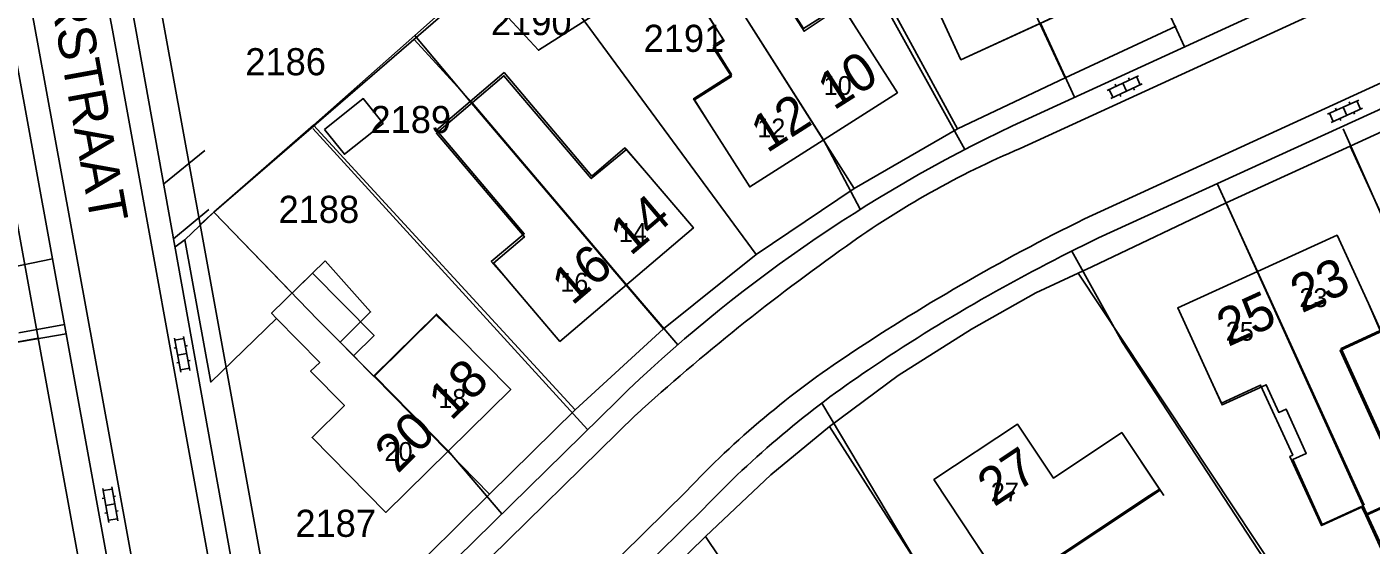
# Model space of a CAD drawing. Extents: x 148816 to 151297, y 399515 to 402500.
# Drawn here: x 149244.9 to 149334.2, y 399907.3 to 399941.7 of the extents above; entities that cross this region are included whole.
import ezdxf

# ---------------------------------------------------------------- set-up
doc = ezdxf.new("R2010")
doc.units = 0
for name, color, linetype in [('B01 Hoofdgebouw  [D] Norm', 7, 'Continuous'), ('B01 Hoofdgebouw  [T] Norm', 7, 'Continuous'), ('B01 hoofgebouw', 7, 'Continuous'), ('B02 Bijgebouw  [D] Norm', 7, 'Continuous'), ('B07 Tussenmuur  [T] Norm', 7, 'Continuous'), ('G01 perceelsgrens', 7, 'Continuous'), ('S02 Open verharding  Norm', 7, 'Continuous'), ('T04 Haag heg  [D] Gem', 7, 'Continuous'), ('V00 Kant verharding algemeen  [T] Norm', 7, 'Continuous'), ('Z01 perceelnummer', 7, 'Continuous'), ('Z02 huisnummer', 7, 'Continuous'), ('Z02 Huisnummer  [Tekst] Norm', 7, 'Continuous'), ('Z06 straatnaam', 7, 'Continuous')]:
    doc.layers.add(name, color=color, linetype=linetype)

msp = doc.modelspace()

# ---------------------------------------------------------------- linework, layer by layer
at = {"layer": 'B01 Hoofdgebouw  [D] Norm'}
for points in [[(149290.26, 399935.28), (149289.272, 399936.83), (149291.725, 399938.394), (149290.517, 399940.289), (149291.238, 399940.749), (149289.636, 399943.26), (149291.201, 399944.259), (149289.588, 399946.785), (149292.089, 399948.382), (149296.556, 399941.387), (149299.081, 399943.065), (149300.06, 399941.53)], [(149277.1, 399924.61), (149275.923, 399925.995), (149277.978, 399927.742), (149272.13, 399934.622), (149276.615, 399938.434), (149282.421, 399931.603), (149284.77, 399933.539), (149285.96, 399932.14)], [(149261.514, 399922.329), (149257.143, 399918.099), (149255.424, 399927.554), (149257.34, 399929.39), (149262.549, 399924.008)], [(149263.909, 399925.338), (149267.998, 399921.189), (149266.63, 399919.841), (149267.956, 399918.495), (149272.136, 399922.615), (149273.56, 399921.17)], [(149323.46, 399918.47), (149324.319, 399916.59), (149327.248, 399917.928), (149328.087, 399916.092), (149328.569, 399916.312), (149329.91, 399913.373), (149329.013, 399912.964), (149330.976, 399908.658), (149333.59, 399909.85), (149333.869, 399909.239), (149336.589, 399910.481), (149332.155, 399920.191), (149334.763, 399921.382), (149334.888, 399921.458), (149334.04, 399923.31)], [(149307.94, 399907.46), (149310.085, 399904.22), (149320.211, 399910.923)]]:
    msp.add_lwpolyline(points, dxfattribs=at)
at = {"layer": 'B01 Hoofdgebouw  [T] Norm'}
for p, q in [((149304.88, 399944.03), (149306.97, 399939.49)), ((149306.97, 399939.49), (149317.54, 399944.36)), ((149302.75, 399937.31), (149300.06, 399941.53)), ((149292.95, 399931.06), (149302.75, 399937.31)), ((149290.26, 399935.28), (149292.95, 399931.06)), ((149289.2, 399928.33), (149285.96, 399932.14)), ((149280.34, 399920.8), (149289.2, 399928.33)), ((149331.96, 399927.85), (149321.38, 399923.02)), ((149334.04, 399923.31), (149331.96, 399927.85)), ((149262.549, 399924.008), (149263.909, 399925.338)), ((149277.1, 399924.61), (149280.34, 399920.8)), ((149264.38, 399919.4), (149261.514, 399922.329)), ((149321.38, 399923.02), (149323.46, 399918.47)), ((149273.56, 399921.17), (149277.07, 399917.61)), ((149263.78, 399918.82), (149264.38, 399919.4)), ((149266.02, 399916.54), (149263.78, 399918.82)), ((149277.07, 399917.61), (149268.77, 399909.45)), ((149263.87, 399914.43), (149266.02, 399916.54)), ((149310.73, 399915.32), (149305.18, 399911.63)), ((149313.12, 399911.73), (149310.73, 399915.32)), ((149268.77, 399909.45), (149263.87, 399914.43)), ((149317.66, 399914.75), (149313.12, 399911.73)), ((149320.211, 399910.923), (149317.66, 399914.75)), ((149305.18, 399911.63), (149307.94, 399907.46))]:
    msp.add_line(p, q, dxfattribs=at)
at = {"layer": 'B01 hoofgebouw'}
for points in [[(149290.26, 399935.281), (149289.21, 399936.91), (149291.74, 399938.52), (149290.53, 399940.43), (149291.19, 399940.85), (149289.58, 399943.39), (149291.23, 399944.43), (149289.61, 399946.98), (149289.68, 399947.03), (149292.07, 399948.55), (149296.51, 399941.56), (149299.02, 399943.15), (149300.06, 399941.531)], [(149304.88, 399944.031), (149306.97, 399939.49), (149317.54, 399944.36), (149315.45, 399948.9)], [(149290.26, 399935.281), (149292.95, 399931.06), (149302.75, 399937.31), (149300.06, 399941.531)], [(149277.1, 399924.61), (149275.78, 399926.1), (149277.97, 399927.95), (149272.14, 399934.83), (149274.38, 399936.73), (149276.63, 399938.64), (149282.45, 399931.77), (149284.65, 399933.64), (149285.96, 399932.14)], [(149277.1, 399924.61), (149280.34, 399920.8), (149289.2, 399928.33), (149285.96, 399932.14)], [(149261.514, 399922.329), (149257.143, 399918.099), (149255.424, 399927.554), (149257.34, 399929.39)], [(149334.04, 399923.31), (149331.96, 399927.85), (149321.38, 399923.02), (149323.46, 399918.47)], [(149261.514, 399922.329), (149261.18, 399922.67), (149264.75, 399926.16)], [(149273.56, 399921.17), (149272.12, 399922.55), (149267.99, 399918.47), (149265.733, 399920.743), (149267.76, 399922.756), (149264.75, 399926.16)], [(149333.64, 399909.98), (149333.93, 399909.35), (149336.66, 399910.6), (149332.22, 399920.33), (149334.83, 399921.52), (149334.04, 399923.31)], [(149273.56, 399921.17), (149277.07, 399917.61), (149268.77, 399909.45), (149263.87, 399914.43), (149266.02, 399916.54), (149263.78, 399918.82), (149264.38, 399919.4), (149261.514, 399922.329)], [(149323.46, 399918.47), (149324.28, 399916.71), (149326.88, 399917.9), (149329.01, 399913.26), (149328.83, 399913.17), (149330.93, 399908.58), (149333.7, 399909.85)], [(149320.44, 399910.58), (149317.66, 399914.75), (149313.12, 399911.73), (149310.73, 399915.32), (149305.18, 399911.63), (149307.94, 399907.46)], [(149319.495, 399910.568), (149320.155, 399911.006)], [(149307.94, 399907.46), (149310.03, 399904.28), (149319.495, 399910.568)]]:
    msp.add_lwpolyline(points, dxfattribs=at)
at = {"layer": 'B02 Bijgebouw  [D] Norm'}
msp.add_lwpolyline([(149268.691, 399958.487), (149269.277, 399955.441), (149274.31, 399956.364), (149275.058, 399951.314), (149272.262, 399950.778), (149272.971, 399947.123), (149271.361, 399945.69), (149273.526, 399943.341), (149274.88, 399944.497), (149278.908, 399940.131), (149282.478, 399942.384)], dxfattribs=at)
msp.add_lwpolyline([(149264.705, 399934.868), (149267.278, 399936.917), (149268.591, 399935.269), (149266.018, 399933.22)], close=True, dxfattribs=at)
at = {"layer": 'B07 Tussenmuur  [T] Norm'}
for p, q in [((149297.85, 399934.185), (149291.36, 399944.361)), ((149284.77, 399924.565), (149274.506, 399936.642)), ((149326.67, 399925.435), (149333.751, 399909.924)), ((149272.92, 399913.53), (149267.998, 399918.536))]:
    msp.add_line(p, q, dxfattribs=at)
at = {"layer": 'G01 perceelsgrens'}
for points in [[(149300.56, 399967.54), (149307.02, 399953.24), (149308.46, 399950.09), (149309.3, 399948.28), (149312.22, 399941.91), (149313.9, 399938.29)], [(149290.46, 399964.82), (149293.95, 399958.5), (149294.23, 399958.63), (149297.78, 399951.64), (149297.67, 399951.58), (149306.74, 399934.91)], [(149280.18, 399962.03), (149289.68, 399947.03), (149299.88, 399930.96)], [(149252.94, 399947.74), (149256.45, 399928.57)], [(149270.69, 399941.11), (149277.94, 399947.54)], [(149277.94, 399947.54), (149293.37, 399926.57)], [(149263.98, 399935.16), (149270.69, 399941.11)], [(149270.69, 399941.11), (149274.38, 399936.73), (149284.74, 399924.53), (149287.21, 399921.63)], [(149313.9, 399938.29), (149321.28, 399941.73)], [(149306.74, 399934.91), (149313.9, 399938.29)], [(149332.82, 399933.76), (149341.05, 399937.51)], [(149242.794, 399936.73), (149245.678, 399921.012)], [(149257.34, 399929.39), (149263.98, 399935.16)], [(149263.98, 399935.16), (149281.35, 399916.26)], [(149299.88, 399930.96), (149306.74, 399934.91)], [(149324.6, 399930), (149332.82, 399933.76)], [(149332.82, 399933.76), (149342.22, 399913.25), (149344.91, 399907.44), (149349.27, 399897.86)], [(149293.37, 399926.57), (149299.88, 399930.96)], [(149314.77, 399925.34), (149315.66, 399925.76), (149324.6, 399930)], [(149324.6, 399930), (149333.64, 399909.98), (149341.02, 399894.11)], [(149256.45, 399928.57), (149257.34, 399929.39)], [(149256.45, 399928.57), (149260.79, 399904.71), (149261.45, 399903.1), (149262.72, 399902), (149264.24, 399901.49), (149265.83, 399901.64), (149267.43, 399902.53)], [(149257.34, 399929.39), (149264.26, 399922.24), (149267.99, 399918.47), (149272.9, 399913.49), (149275.66, 399910.66)], [(149287.21, 399921.63), (149293.37, 399926.57)], [(149298.24, 399915.16), (149302.81, 399918.53), (149307.67, 399921.62), (149311.95, 399924.02), (149314.77, 399925.34)], [(149314.77, 399925.34), (149336.78, 399892.15), (149337.35, 399892.41)], [(149281.35, 399916.26), (149287.21, 399921.63)], [(149206.264, 399913.847), (149245.678, 399921.012)], [(149245.678, 399921.012), (149248.834, 399903.809)], [(149275.66, 399910.66), (149281.35, 399916.26)], [(149290, 399907.85), (149294.34, 399911.95), (149298.24, 399915.16)], [(149298.24, 399915.16), (149360.36, 399818.02)], [(149267.43, 399902.53), (149275.66, 399910.66)], [(149282.68, 399900.69), (149290, 399907.85)], [(149290, 399907.85), (149298.48, 399895.24), (149298.61, 399895.35), (149302.25, 399891.45), (149301.5, 399890.76), (149312.7, 399874.21)]]:
    msp.add_lwpolyline(points, dxfattribs=at)
at = {"layer": 'S02 Open verharding  Norm'}
for p, q in [((149316.685, 399937.456), (149318.765, 399938.438)), ((149318.885, 399937.832), (149318.629, 399938.374)), ((149317.077, 399936.978), (149316.821, 399937.52)), ((149316.941, 399936.914), (149319.021, 399937.896)), ((149317.209, 399937.869), (149317.273, 399937.734)), ((149317.725, 399937.947), (149317.981, 399937.405)), ((149318.113, 399938.296), (149318.177, 399938.161)), ((149318.433, 399937.618), (149318.497, 399937.483)), ((149317.529, 399937.191), (149317.593, 399937.056)), ((149331.312, 399935.886), (149333.412, 399936.822)), ((149332.757, 399936.695), (149332.818, 399936.558)), ((149333.519, 399936.213), (149333.275, 399936.761)), ((149331.693, 399935.399), (149331.449, 399935.947)), ((149331.556, 399935.338), (149333.656, 399936.274)), ((149331.844, 399936.287), (149331.905, 399936.15)), ((149332.362, 399936.354), (149332.606, 399935.806)), ((149333.063, 399936.01), (149333.124, 399935.873)), ((149332.15, 399935.602), (149332.211, 399935.465)), ((149254.742, 399921.026), (149255.16, 399918.765)), ((149254.769, 399920.879), (149255.359, 399920.988)), ((149255.332, 399921.135), (149255.75, 399918.874)), ((149255.597, 399920.524), (149255.45, 399920.496)), ((149254.86, 399920.387), (149254.713, 399920.36)), ((149255.541, 399920.005), (149254.951, 399919.895)), ((149255.042, 399919.404), (149254.895, 399919.376)), ((149255.133, 399918.912), (149255.723, 399919.021)), ((149255.779, 399919.54), (149255.632, 399919.513)), ((149249.976, 399911.047), (149250.377, 399908.782)), ((149250.002, 399910.899), (149250.593, 399911.004)), ((149250.567, 399911.152), (149250.968, 399908.887)), ((149250.089, 399910.407), (149249.942, 399910.381)), ((149250.767, 399910.019), (149250.177, 399909.915)), ((149250.828, 399910.538), (149250.68, 399910.512)), ((149250.264, 399909.422), (149250.116, 399909.396)), ((149250.351, 399908.93), (149250.942, 399909.035)), ((149251.002, 399909.553), (149250.855, 399909.527))]:
    msp.add_line(p, q, dxfattribs=at)
at = {"layer": 'T04 Haag heg  [D] Gem'}
for p, q in [((149321.816, 399940.35), (149308.446, 399969.506)), ((149297.394, 399951.291), (149307.228, 399933.54)), ((149257.34, 399929.39), (149273.526, 399943.341)), ((149314.513, 399937.001), (149312.255, 399941.925)), ((149274.506, 399936.642), (149270.664, 399940.829)), ((149263.918, 399934.925), (149282.176, 399914.947)), ((149332.372, 399934.921), (149342.029, 399913.046)), ((149297.85, 399934.185), (149300.275, 399929.57)), ((149324, 399931.273), (149326.67, 399925.435)), ((149254.773, 399927.083), (149255.424, 399927.554)), ((149314.341, 399926.801), (149317.696, 399920.74)), ((149284.77, 399924.565), (149288.174, 399920.58)), ((149317.696, 399920.74), (149335.962, 399892.865)), ((149297.731, 399916.71), (149309.144, 399897.562)), ((149272.92, 399913.53), (149276.476, 399909.361)), ((149333.869, 399909.239), (149340.844, 399893.968))]:
    msp.add_line(p, q, dxfattribs=at)
msp.add_lwpolyline([(149247.548, 399921.306), (149235.38, 399919.23)], dxfattribs=at)
at = {"layer": 'V00 Kant verharding algemeen  [T] Norm'}
for p, q in [((149234.85, 400000), (149245.68, 399940.42)), ((149239.96, 400000), (149250.61, 399941.45)), ((149252.15, 399941.62), (149241.52, 400000)), ((149381.98, 399967.94), (149310.39, 399935.11)), ((149310.91, 399933.61), (149382.57, 399966.46)), ((149384.89, 399960.88), (149315.71, 399929.19)), ((149385.53, 399959.41), (149316.12, 399927.67)), ((149250.61, 399941.45), (149257.78, 399902.02)), ((149259.23, 399902.39), (149252.15, 399941.62)), ((149244.07, 399940.37), (149253.22, 399890.22)), ((149245.68, 399940.42), (149254.95, 399889.64)), ((149284.18, 399916.91), (149266.87, 399899.95)), ((149267.9, 399898.8), (149285.39, 399915.93)), ((149288.74, 399910.87), (149256.31, 399878.93)), ((149289.88, 399909.69), (149257.46, 399877.84))]:
    msp.add_line(p, q, dxfattribs=at)
for points in [[(149256.747, 399933.478), (149254.018, 399931.269)], [(149254.677, 399927.616), (149257.019, 399929.567)], [(149246.64, 399926.284), (149243.209, 399925.575)], [(149244.391, 399921.367), (149247.435, 399921.928)]]:
    msp.add_lwpolyline(points, dxfattribs=at)
for centre, radius, start, end in [((149352.321, 399846.752), 97.803, 115.38709, 134.16446), ((149334.014, 399878.949), 59.343, 112.91289, 125.71772), ((149376.283, 399804.626), 138.51, 115.93268, 123.6259), ((149367.557, 399820.13), 119.208, 115.56197, 124.03272), ((149383.78, 399807.444), 146.457, 125.19367, 132.20586), ((149333.205, 399868.853), 61.176, 123.34226, 136.6215), ((149336.703, 399865.213), 64.581, 123.73317, 136.47186)]:
    msp.add_arc(centre, radius, start, end, dxfattribs=at)

# ---------------------------------------------------------------- texts
at = {"layer": 'Z01 perceelnummer'}
for s, p in [('2190', (149275.755, 399941.129)), ('2191', (149285.895, 399940.017)), ('2186', (149259.441, 399938.464)), ('2189', (149267.756, 399934.628)), ('2188', (149261.65, 399928.667)), ('2187', (149262.766, 399907.83))]:
    msp.add_text(s, height=1.8, dxfattribs=at).set_placement(p)
at = {"layer": 'Z02 huisnummer'}
for s, rotation, p in [('10', 32.54589, (149298.525, 399936.098)), ('12', 32.54589, (149294.087, 399933.267)), ('14', 40.37763, (149285.026, 399926.424)), ('16', 40.37763, (149281.154, 399923.133)), ('23', 24.51507, (149329.611, 399922.655)), ('25', 24.51507, (149324.72, 399920.422)), ('18', 44.51377, (149273.108, 399915.47)), ('20', 44.51377, (149269.555, 399911.977)), ('27', 33.57881, (149309.176, 399909.783))]:
    msp.add_text(s, height=2.5, rotation=rotation, dxfattribs=at).set_placement(p)
at = {"layer": 'Z02 Huisnummer  [Tekst] Norm'}
for s, p in [('10', (149297.86, 399937.16)), ('12', (149293.45, 399934.34)), ('14', (149284.25, 399927.4)), ('16', (149280.36, 399924.1)), ('23', (149329.46, 399923.08)), ('25', (149324.57, 399920.85)), ('18', (149272.26, 399916.39)), ('20', (149268.69, 399912.87)), ('27', (149308.96, 399910.18))]:
    msp.add_text(s, height=1.25, dxfattribs=at).set_placement(p)
at = {"layer": 'Z06 straatnaam'}
msp.add_text('VELDAKKERSTRAAT', height=2.5, rotation=280.30997, dxfattribs=at).set_placement((149243.263, 399961.248))

doc.saveas('drawing.dxf')
